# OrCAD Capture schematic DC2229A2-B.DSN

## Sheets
1 -A SHEET1: size C; title: HIGH OUTPUT CURRENT  DUAL OUTPUT STEP-DOWN DC-DC CONVERTER; rev: 2; company: TM
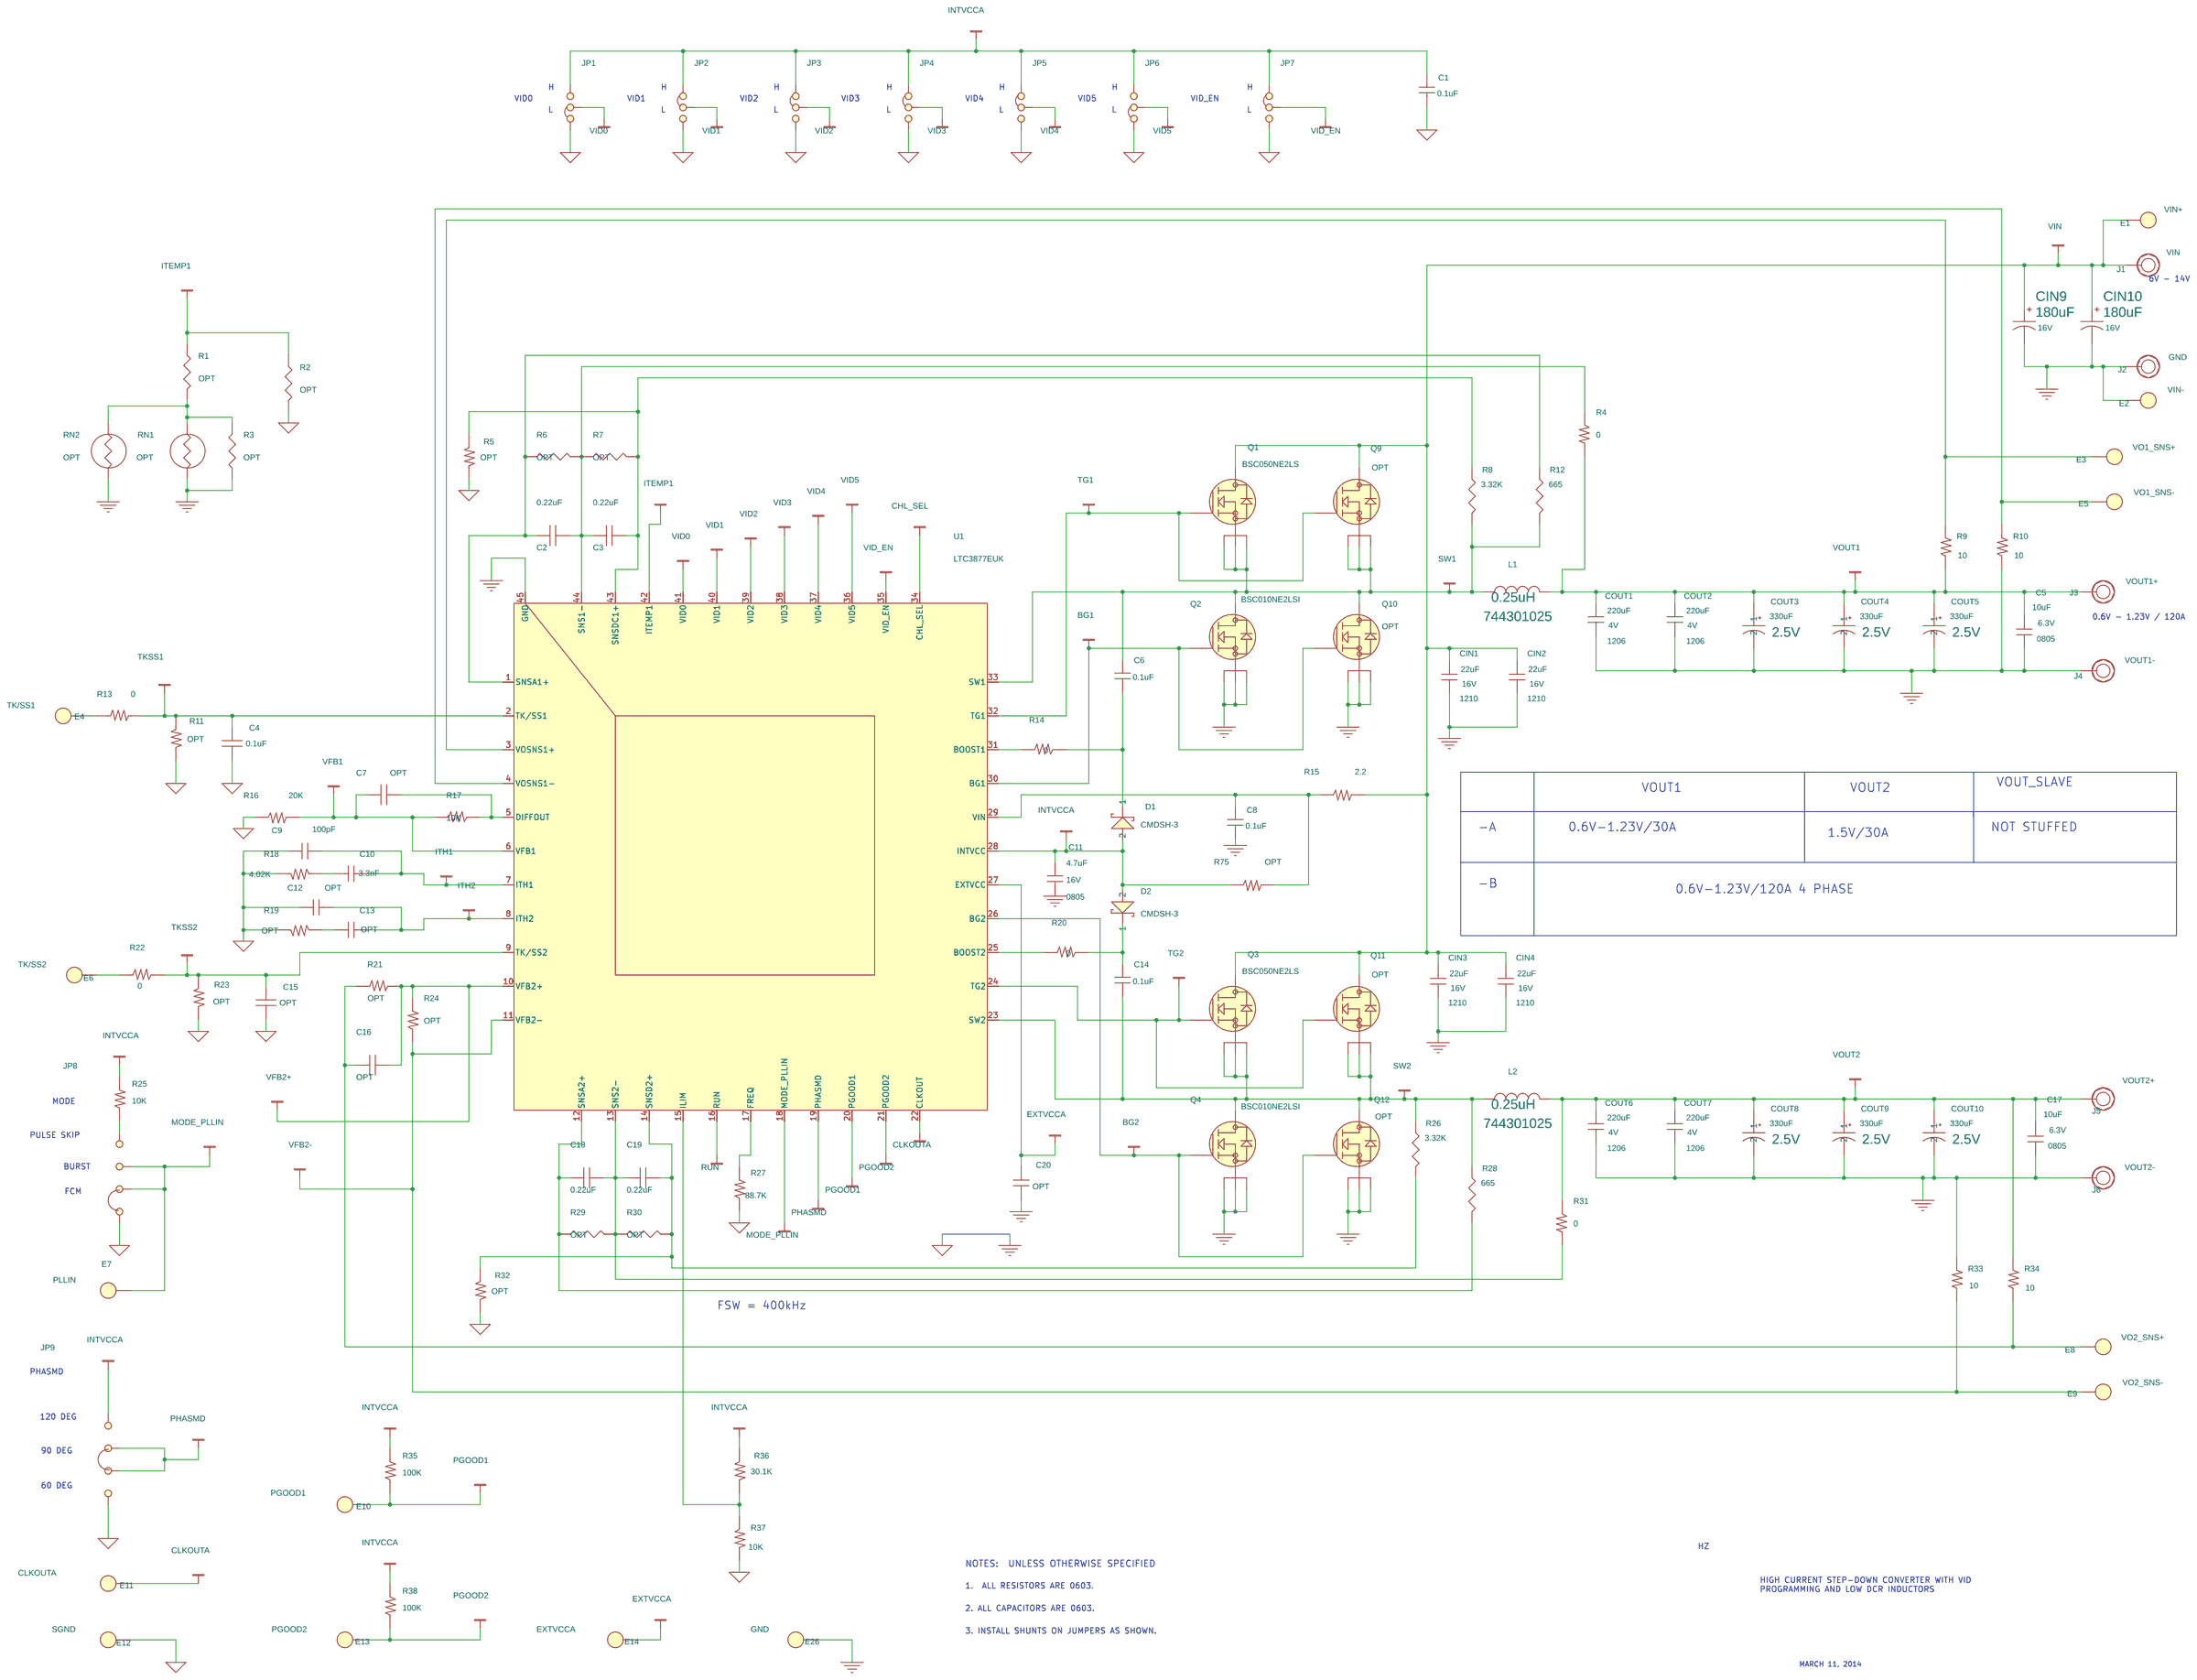
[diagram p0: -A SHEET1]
2 -A SHEET2: size C
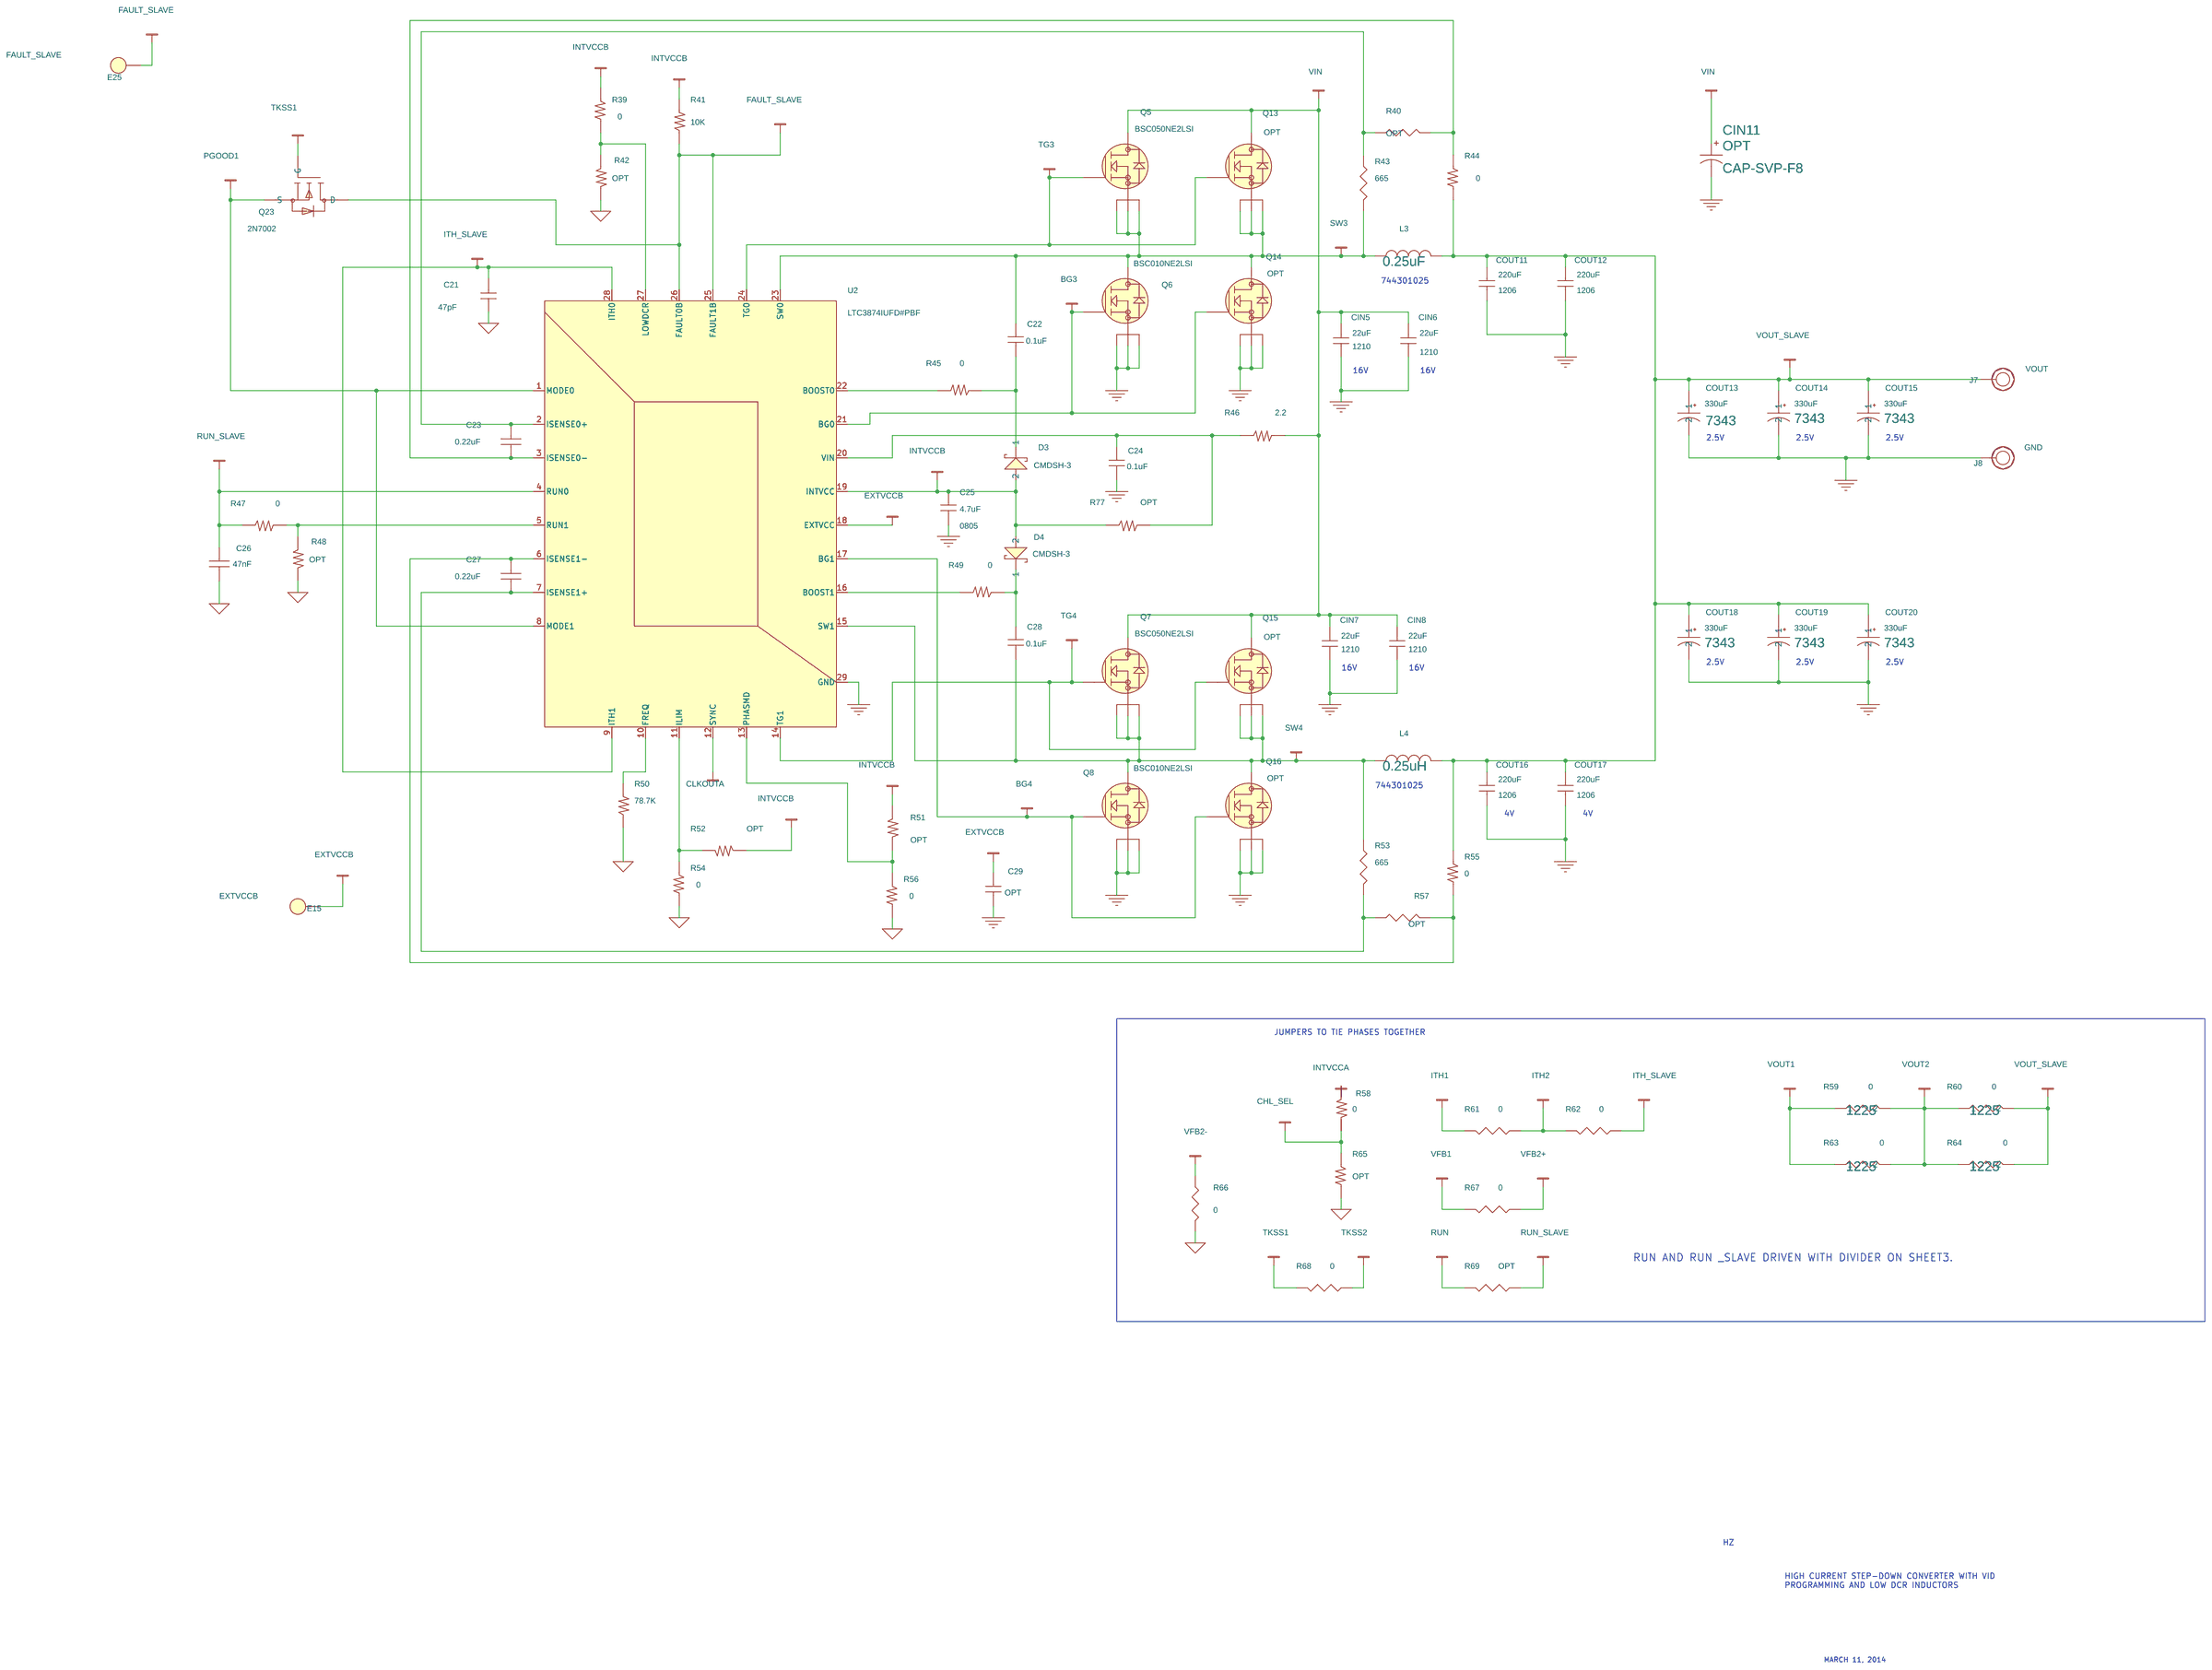
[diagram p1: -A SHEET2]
3 -A SHEET3: size C
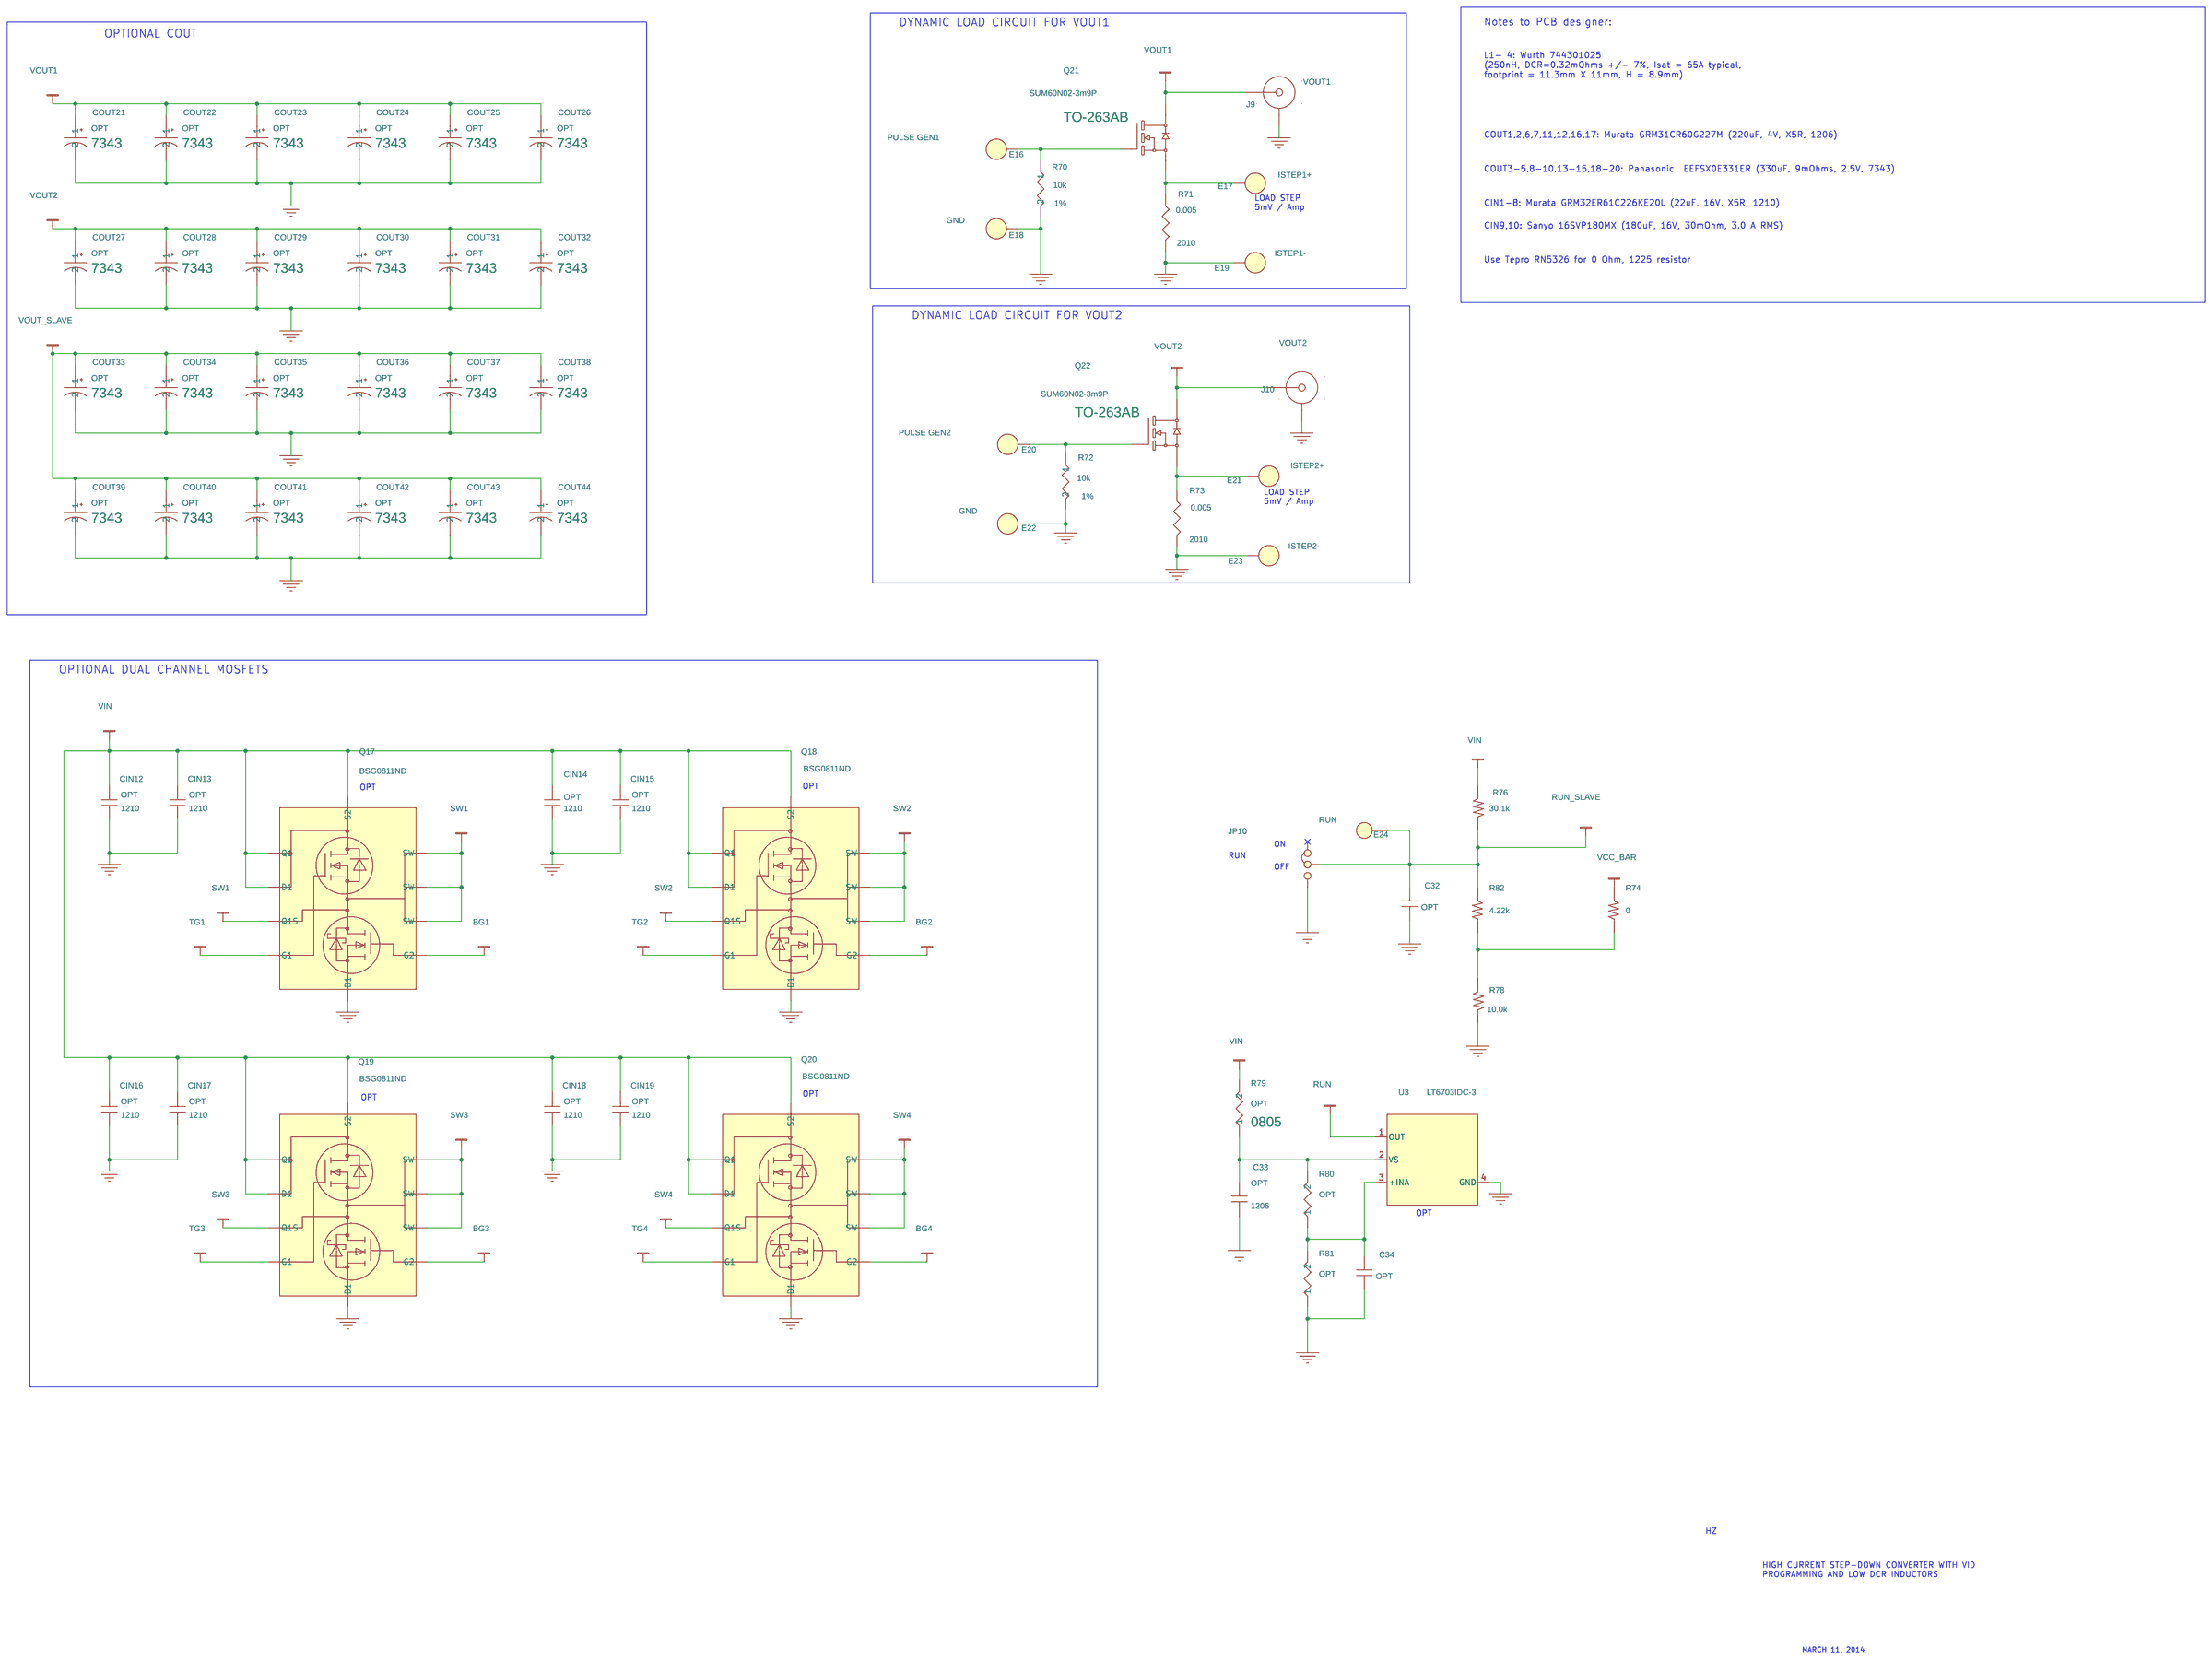
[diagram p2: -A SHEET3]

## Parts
sheet -A SHEET1
C1  0.1uF  [0603]
C2  0.22uF  [0603]
C3  0.22uF  [0603]
C4  0.1uF  [0603]
C5  10uF  [0805]
C6  0.1uF  [0603]
C7  OPT  [0603]
C8  0.1uF  [0603]
C9  100pF  [0603]
C10  3.3nF  [0603]
C11  4.7uF  [0805]
C12  OPT  [0603]
C13  OPT  [0603]
C14  0.1uF  [0603]
C15  OPT  [0603]
C16  OPT  [0603]
C17  10uF  [0805]
C18  0.22uF  [0603]
C19  0.22uF  [0603]
C20  C-0603  [0603]
CIN1  22uF  [1210]
CIN2  22uF  [1210]
CIN3  22uF  [1210]
CIN4  22uF  [1210]
CIN9  180uF  [CAP-SVP-F8]
CIN10  180uF  [CAP-SVP-F8]
COUT1  220uF  [1206]
COUT2  220uF  [1206]
COUT3  330uF  [7343]
COUT4  330uF  [7343]
COUT5  330uF  [7343]
COUT6  220uF  [1206]
COUT7  220uF  [1206]
COUT8  330uF  [7343]
COUT9  330uF  [7343]
COUT10  330uF  [7343]
D1  CMDSH-3  [SOD-323]
D2  CMDSH-3  [SOD-323]
E1  PAD150-094  [PAD150-094]
E2  PAD150-094  [PAD150-094]
E3  PAD150-094  [PAD150-094]
E4  PAD150-094  [PAD150-094]
E5  PAD150-094  [PAD150-094]
E6  PAD150-094  [PAD150-094]
E7  PAD150-094  [PAD150-094]
E8  PAD150-094  [PAD150-094]
E9  PAD150-094  [PAD150-094]
E10  PAD150-094  [PAD150-094]
E11  PAD150-094  [PAD150-094]
E12  PAD150-094  [PAD150-094]
E13  PAD150-094  [PAD150-094]
E14  PAD150-094  [PAD150-094]
E26  PAD150-094  [PAD150-094]
J1  PAD450-190  [CON\LUG\10]
J2  PAD450-190  [CON\LUG\10]
J3  PAD450-190  [CON\LUG\10]
J4  PAD450-190  [CON\LUG\10]
J5  PAD450-190  [CON\LUG\10]
J6  PAD450-190  [CON\LUG\10]
JP1  JMP1X3  [JUMPER3\2MM]
JP2  JMP1X3  [JUMPER3\2MM]
JP3  JMP1X3  [JUMPER3\2MM]
JP4  JMP1X3  [JUMPER3\2MM]
JP5  JMP1X3  [JUMPER3\2MM]
JP6  JMP1X3  [JUMPER3\2MM]
JP7  JMP1X3  [JUMPER3\2MM]
JP8  JP3X1/079\NO\12  [SIP-4P]
JP9  JP3X1/079\NO\12  [SIP-4P]
L1  0.25uH  [744301025]
L2  0.25uH  [744301025]
Q1  BSC050NE2LS  [LFPAK]
Q2  BSC010NE2LSI  [LFPAK]
Q3  BSC050NE2LS  [LFPAK]
Q4  BSC010NE2LSI  [LFPAK]
Q9  LFPAK-OPT  [LFPAK]
Q10  LFPAK-OPT  [LFPAK]
Q11  LFPAK-OPT  [LFPAK]
Q12  LFPAK-OPT  [LFPAK]
R1  OPT  [0603]
R2  OPT  [0603]
R3  OPT  [0603]
R4  0  [0603]
R5  R-0603  [0603]
R6  OPT  [0603]
R7  OPT  [0603]
R8  3.32K  [0603]
R9  10  [0603]
R10  10  [0603]
R11  R-0603  [0603]
R12  665  [0603]
R13  0  [0603]
R14  0  [0603]
R15  2.2  [0603]
R16  20K  [0603]
R17  10K  [0603]
R18  4.02K  [0603]
R19  OPT  [0603]
R20  0  [0603]
R21  OPT  [0603]
R22  0  [0603]
R23  R-0603  [0603]
R24  OPT  [0603]
R25  10K  [0603]
R26  3.32K  [0603]
R27  88.7K  [0603]
R28  665  [0603]
R29  OPT  [0603]
R30  OPT  [0603]
R31  0  [0603]
R32  R-0603  [0603]
R33  10  [0603]
R34  10  [0603]
R35  100K  [0603]
R36  R-0603  [0603]
R37  R-0603  [0603]
R38  100K  [0603]
R75  OPT  [0603]
RN1  OPT  [0603]
RN2  OPT  [0603]
U1  LTC3877EUK  [QFN_44_7MMX7MM_UK]
sheet -A SHEET2
C21  47pF  [0603]
C22  0.1uF  [0603]
C23  0.22uF  [0603]
C24  0.1uF  [0603]
C25  4.7uF  [0805]
C26  47nF  [0603]
C27  0.22uF  [0603]
C28  0.1uF  [0603]
C29  C-0603  [0603]
CIN5  22uF  [1210]
CIN6  22uF  [1210]
CIN7  22uF  [1210]
CIN8  22uF  [1210]
CIN11  OPT  [CAP-SVP-F8]
COUT11  220uF  [1206]
COUT12  220uF  [1206]
COUT13  330uF  [7343]
COUT14  330uF  [7343]
COUT15  330uF  [7343]
COUT16  220uF  [1206]
COUT17  220uF  [1206]
COUT18  330uF  [7343]
COUT19  330uF  [7343]
COUT20  330uF  [7343]
D3  CMDSH-3  [SOD-323]
D4  CMDSH-3  [SOD-323]
E15  PAD150-094  [PAD150-094]
E25  PAD150-094  [PAD150-094]
J7  OPT  [CON\LUG\10]
J8  OPT  [CON\LUG\10]
L3  0.25uF  [744301025]
L4  0.25uH  [744301025]
Q5  BSC050NE2LSI  [LFPAK]
Q6  BSC010NE2LSI  [LFPAK]
Q7  BSC050NE2LSI  [LFPAK]
Q8  BSC010NE2LSI  [LFPAK]
Q13  LFPAK-OPT  [LFPAK]
Q14  LFPAK-OPT  [LFPAK]
Q15  LFPAK-OPT  [LFPAK]
Q16  LFPAK-OPT  [LFPAK]
Q23  2N7002  [SOT-23]
R39  0  [0603]
R40  OPT  [0603]
R41  10K  [0603]
R42  R-0603  [0603]
R43  665  [0603]
R44  0  [0603]
R45  0  [0603]
R46  2.2  [0603]
R47  0  [0603]
R48  R-0603  [0603]
R49  0  [0603]
R50  78.7K  [0603]
R51  OPT  [0603]
R52  OPT  [0603]
R53  665  [0603]
R54  R-0603  [0603]
R55  0  [0603]
R56  R-0603  [0603]
R57  OPT  [0603]
R58  R-0603  [0603]
R59  0  [1225]
R60  0  [1225]
R61  0  [0603]
R62  0  [0603]
R63  0  [1225]
R64  0  [1225]
R65  OPT  [0603]
R66  0  [0603]
R67  0  [0603]
R68  0  [0603]
R69  OPT  [0603]
R77  OPT  [0603]
U2  LTC3874IUFD#PBF  [QFN_28_4MMX5MM_UFD]
sheet -A SHEET3
C32  C-0603  [0603]
C33  OPT  [1206]
C34  C-0603  [0603]
CIN12  OPT  [1210]
CIN13  OPT  [1210]
CIN14  OPT  [1210]
CIN15  OPT  [1210]
CIN16  OPT  [1210]
CIN17  OPT  [1210]
CIN18  OPT  [1210]
CIN19  OPT  [1210]
COUT21  OPT  [7343]
COUT22  OPT  [7343]
COUT23  OPT  [7343]
COUT24  OPT  [7343]
COUT25  OPT  [7343]
COUT26  OPT  [7343]
COUT27  OPT  [7343]
COUT28  OPT  [7343]
COUT29  OPT  [7343]
COUT30  OPT  [7343]
COUT31  OPT  [7343]
COUT32  OPT  [7343]
COUT33  OPT  [7343]
COUT34  OPT  [7343]
COUT35  OPT  [7343]
COUT36  OPT  [7343]
COUT37  OPT  [7343]
COUT38  OPT  [7343]
COUT39  OPT  [7343]
COUT40  OPT  [7343]
COUT41  OPT  [7343]
COUT42  OPT  [7343]
COUT43  OPT  [7343]
COUT44  OPT  [7343]
E16  Testpoint  [PAD150-094]
E17  Testpoint  [PAD150-094]
E18  Testpoint  [PAD150-094]
E19  Testpoint  [PAD150-094]
E20  Testpoint  [PAD150-094]
E21  Testpoint  [PAD150-094]
E22  Testpoint  [PAD150-094]
E23  Testpoint  [PAD150-094]
E24  PAD150-094  [PAD150-094]
J9  Connector  [BNC]
J10  Connector  [BNC]
JP10  JMP1X3  [JUMPER3\2MM]
Q17  BSG0811ND  [PG-TISON8-4]
Q18  BSG0811ND  [PG-TISON8-4]
Q19  BSG0811ND  [PG-TISON8-4]
Q20  BSG0811ND  [PG-TISON8-4]
Q21  SUD50N03-12P  [TO-263AB]
Q22  SUD50N03-12P  [TO-263AB]
R70  10k  [0603]
R71  0.005  [2010]
R72  10k  [0603]
R73  0.005  [2010]
R74  0  [0603]
R76  R-0603  [0603]
R78  R-0603  [0603]
R79  OPT  [0805]
R80  OPT  [0603]
R81  OPT  [0603]
R82  4.22k  [0603]
U3  LT6703IDC-3  [DFN3DC]

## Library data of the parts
C1 C8 C24 = CAP-NP: Voltage: 50V
C2 C3 C18 C19 C23 C27 = EMK107BJ224MA: CAP, 0603 0.22uF 10% 25V X7R; Part Number: TDK C1608X7R1E224K
C4 C7 C15 C16 C26 = EMK107BJ224MA: CAP, X5R, 0.01uF, 25V,10%, 0603; 4th Part Field: AVX; 5th Part Field: 06033C103KAT2A; Part Number: TDK C1608X7R1E224K
C5 C17 = CAP-NP: CAP, 1210 22uF 10% 16V X5R; Part Number: MURATA GRM32ER61C226KE20L; Voltage rating: 6.3V
C6 C11 C14 C22 C25 C28 C33 = CAP-NP: Voltage: 16V
C9 C12 C21 = CAP-NP: CAP, 0603, 100pF; Part Number: TDK C1608X7R1E104K
C10 C13 = CAP-NP: CAP, 0603, 470pF; Part Number: TDK C1608X7R1E104K
C20 C29 C32 C34 = CAP-NP: CAP, 0603; COMPFIXED: OPT; Part Number: TDK C1608X7R1E104K
CIN1-CIN8 CIN12-CIN19 = CAP-NP: CAP, 1210 22uF 10% 16V X5R; Part Number: MURATA GRM32ER61C226KE20L; Voltage rating: 16V
CIN9-CIN11 = CAP: CAP, 180uF 16V; 1ST PART FIELD: 16V; COMPFIXED: Sanyo; COMPGROUP: 16SVP180MX
COUT1 COUT2 COUT6 COUT7 COUT11 COUT12 COUT16 COUT17 = CAP-NP: CAP, 1206 100uF 20% 6.3V X5R; Part Number: MURATA GRM31CR60J107ME39L; Voltage: 4V
COUT3 COUT15 COUT34 = tant_4: CAP, 7343 330uF 20% 2.5V POSCAP; Part Number: SANYO 2R5TPE330M9; Voltage: 2.5V
COUT4 COUT14 COUT24 = tant_3: CAP, 7343 330uF 20% 2.5V POSCAP; Part Number: SANYO 2R5TPE330M9; Voltage: 2.5V
COUT5 COUT20 COUT36 = tant: CAP, 7343 330uF 20% 2.5V POSCAP; Part Number: SANYO 2R5TPE330M9; Voltage: 2.5V
COUT8 COUT19 COUT30 = tant_5: CAP, 7343 330uF 20% 2.5V POSCAP; Part Number: SANYO 2R5TPE330M9; Voltage: 2.5V
COUT9 COUT13 COUT22 = tant_1: CAP, 7343 330uF 20% 2.5V POSCAP; Part Number: SANYO 2R5TPE330M9; Voltage: 2.5V
COUT10 COUT18 COUT35 = tant_2: CAP, 7343 330uF 20% 2.5V POSCAP; Part Number: SANYO 2R5TPE330M9; Voltage: 2.5V
D1 D4 = DIODE-SCHOTTKY_0_1
D2 D3 = DIODE-SCHOTTKY_0
E1 = E: TURRET; COMPFIXED: VIN+; Part Number: MILL-MAX 2501-2-00-80-00-00-07-0
E2 = E: TURRET; COMPFIXED: VIN-; Part Number: MILL-MAX 2501-2-00-80-00-00-07-0
E3 = E: TURRET; COMPFIXED: VO1_SNS+; Part Number: MILL-MAX 2501-2-00-80-00-00-07-0
E4 = E: COMPFIXED: TK/SS1
E5 = E: TURRET; COMPFIXED: VO1_SNS-; Part Number: MILL-MAX 2501-2-00-80-00-00-07-0
E6 = E: COMPFIXED: TK/SS2
E7 = E: COMPFIXED: PLLIN
E8 = E: TURRET; COMPFIXED: VO2_SNS+; Part Number: MILL-MAX 2501-2-00-80-00-00-07-0
E9 = E: TURRET; COMPFIXED: VO2_SNS-; Part Number: MILL-MAX 2501-2-00-80-00-00-07-0
E10 = E: COMPFIXED: PGOOD1
E11 = E: COMPFIXED: CLKOUTA
E12 = E: COMPFIXED: SGND
E13 = E: COMPFIXED: PGOOD2
E14 = E: COMPFIXED: EXTVCCA
E26 = E: COMPFIXED: GND
J1 = E-KEY-575: JACK, BANANA; COMPFIXED: VIN; Part Number: KEYSTONE 575-4
J2 J8 = E-KEY-575: JACK, BANANA; COMPFIXED: GND; Part Number: KEYSTONE 575-4
J3 = E-KEY-575: JACK, BANANA; COMPFIXED: VOUT1+; Part Number: KEYSTONE 575-4
J4 = E-KEY-575: JACK, BANANA; COMPFIXED: VOUT1-; Part Number: KEYSTONE 575-4
J5 = E-KEY-575: JACK, BANANA; COMPFIXED: VOUT2+; Part Number: KEYSTONE 575-4
J6 = E-KEY-575: JACK, BANANA; COMPFIXED: VOUT2-; Part Number: KEYSTONE 575-4
JP1 = JMP1X3_8: HEADER,3PIN, 2mm; Part Number: SAMTEC TMM-103-02-L-S
JP2-JP5 JP7 JP10 = JMP1X3_0: HEADER,3PIN, 2mm; Part Number: SAMTEC TMM-103-02-L-S
JP6 = JMP1X3_9: HEADER,3PIN, 2mm; Part Number: SAMTEC TMM-103-02-L-S
JP8 = JP3X1_079_NO_12_0
JP9 = JP3X1_079_NO_12_5
L1-L4 = IND
Q1 Q3 Q5 Q7 = MOSFET_N-DIODE-A-LFPAK_0
Q2 Q4 Q6 Q8 = MOSFET_N-DIODE-A-LFPAK
Q9-Q16 = MOSFET_N-DIODE-A-LFPAK: COMPFIXED: OPT
R1-R3 R6 R7 R29 R30 R40 R57 R61 R62 R66-R69 = R: RES, 0603 OPTION; Part Number: OPTION
R4 R13-R17 R20-R22 R24 R25 R27 R31 R35 R38 R39 R41 R44-R47 R49-R52 R55 R65 R74 R75 R77 R82 = R_v2
R5 R11 R23 R32 R42 R48 = R_v2: RES, 0603; COMPFIXED: OPT; Part Number: PANASONIC ERJ3GEY0R00V
R8 R12 R26 R28 R43 R53 = CRCW06032K87FKEA
R9 R10 R33 R34 = R_v2: RES, 0603; Part Number: PANASONIC ERJ3GEY0R00V
R18 R19 = R_v2: RES, 0603, 10K; Part Number: PANASONIC ERJ3GEY0R00V
R36 = R_v2: RES, 0603; COMPFIXED: 30.1K; Part Number: PANASONIC ERJ3GEY0R00V
R37 = R_v2: RES, 0603; COMPFIXED: 10K; Part Number: PANASONIC ERJ3GEY0R00V
RN1 RN2 = RNTC: THERMISTOR, 0805 100K OHMS 5% / 0603 4250 OHMS 2%; Part Number: MURATA NCP18WF104J03RB /
U1 = LTC1629_26: IC, LTC3838EUHF; Part Number: LINEAR TECH. LTC3838EUHF
E15 = E: COMPFIXED: EXTVCCB
E25 = E: COMPFIXED: FAULT_SLAVE
J7 = E-KEY-575: JACK, BANANA; COMPFIXED: VOUT; Part Number: KEYSTONE 575-4
Q23 = TRANSISTOR_0: XSTR, N-CHANNEL DMOS FET; Part Number: FAIRCHILD 2N7002A
R54 R56 R58 = R_v2: RES, 0603; COMPFIXED: 0; Part Number: PANASONIC ERJ3GEY0R00V
R59 = CR16-104JM_3: RES, OPT, 2512
R60 = CR16-104JM_2: RES, OPT, 2512
R63 = CR16-104JM_1: RES, OPT, 2512
R64 = CR16-104JM: RES, OPT, 2512
U2 = LTC3880-M0001_1: IC, POLYPHASE STEP-DOWN SYNCHRONOUS SLAVE CONTROLLER; Component: IC; Manufacturer: LTC; Manufacturer P/N: LTC3880_M0001; Part Number: LINEAR TECH.LTC3874IUFD#PBF; Part Type: LTC3880EUF
COUT21 = tant_22: CAP, 7343 330uF 20% 2.5V POSCAP; Part Number: SANYO 2R5TPE330M9; Voltage: 2.5V
COUT23 = tant_21: CAP, 7343 330uF 20% 2.5V POSCAP; Part Number: SANYO 2R5TPE330M9; Voltage: 2.5V
COUT25 = tant_20: CAP, 7343 330uF 20% 2.5V POSCAP; Part Number: SANYO 2R5TPE330M9; Voltage: 2.5V
COUT26 = tant_16: CAP, 7343 330uF 20% 2.5V POSCAP; Part Number: SANYO 2R5TPE330M9; Voltage: 2.5V
COUT27 = tant_17: CAP, 7343 330uF 20% 2.5V POSCAP; Part Number: SANYO 2R5TPE330M9; Voltage: 2.5V
COUT28 = tant_8: CAP, 7343 330uF 20% 2.5V POSCAP; Part Number: SANYO 2R5TPE330M9; Voltage: 2.5V
COUT29 = tant_6: CAP, 7343 330uF 20% 2.5V POSCAP; Part Number: SANYO 2R5TPE330M9; Voltage: 2.5V
COUT31 = tant_14: CAP, 7343 330uF 20% 2.5V POSCAP; Part Number: SANYO 2R5TPE330M9; Voltage: 2.5V
COUT32 = tant_12: CAP, 7343 330uF 20% 2.5V POSCAP; Part Number: SANYO 2R5TPE330M9; Voltage: 2.5V
COUT33 = tant_11: CAP, 7343 330uF 20% 2.5V POSCAP; Part Number: SANYO 2R5TPE330M9; Voltage: 2.5V
COUT37 = tant_9: CAP, 7343 330uF 20% 2.5V POSCAP; Part Number: SANYO 2R5TPE330M9; Voltage: 2.5V
COUT38 = tant_7: CAP, 7343 330uF 20% 2.5V POSCAP; Part Number: SANYO 2R5TPE330M9; Voltage: 2.5V
COUT39 = tant_19: CAP, 7343 330uF 20% 2.5V POSCAP; Part Number: SANYO 2R5TPE330M9; Voltage: 2.5V
COUT40 = tant_18: CAP, 7343 330uF 20% 2.5V POSCAP; Part Number: SANYO 2R5TPE330M9; Voltage: 2.5V
COUT41 = tant_13: CAP, 7343 330uF 20% 2.5V POSCAP; Part Number: SANYO 2R5TPE330M9; Voltage: 2.5V
COUT42 = tant_10: CAP, 7343 330uF 20% 2.5V POSCAP; Part Number: SANYO 2R5TPE330M9; Voltage: 2.5V
COUT43 = tant_23: CAP, 7343 330uF 20% 2.5V POSCAP; Part Number: SANYO 2R5TPE330M9; Voltage: 2.5V
COUT44 = tant_15: CAP, 7343 330uF 20% 2.5V POSCAP; Part Number: SANYO 2R5TPE330M9; Voltage: 2.5V
E16 = MillMax-2501: TURRET; 9th Part Field: PULSE GEN1; Part Number: MILL MAX 2501-2-00-80-00-00-07-0
E17 = MillMax-2501: TURRET; 9th Part Field: ISTEP1+; Part Number: MILL MAX 2501-2-00-80-00-00-07-0
E18 E22 = MillMax-2501: TURRET; 9th Part Field: GND; Part Number: MILL MAX 2501-2-00-80-00-00-07-0
E19 = MillMax-2501: TURRET; 9th Part Field: ISTEP1-; Part Number: MILL MAX 2501-2-00-80-00-00-07-0
E20 = MillMax-2501: TURRET; 9th Part Field: PULSE GEN2; Part Number: MILL MAX 2501-2-00-80-00-00-07-0
E21 = MillMax-2501: TURRET; 9th Part Field: ISTEP2+; Part Number: MILL MAX 2501-2-00-80-00-00-07-0
E23 = MillMax-2501: TURRET; 9th Part Field: ISTEP2-; Part Number: MILL MAX 2501-2-00-80-00-00-07-0
E24 = E: COMPFIXED: RUN
J9 = Connex_112404_gnd2_0: CON, BNC, 5 PINS; 10th Part Field: 5% DUTY CYCLE MAX.; 11th Part Field: 10mV / A; 9th Part Field: VOUT1; Part Number: CONNEX 112404
J10 = Connex_112404_gnd2_0_1: CON, BNC, 5 PINS; 10th Part Field: 5% DUTY CYCLE MAX.; 11th Part Field: 10mV / A; 9th Part Field: VOUT2; Part Number: CONNEX 112404
Q17-Q20 = FDMS3602S_8
Q21 Q22 = Si7806BDN_0: XSTR, MOSFET; 5th Part Field: SUM60N02-3m9P; Part Number: VISHAY SILICONIX SUD50N03-12P
R70 = CR16-103JM_3: RES, 0603 10K OHMS 1% 1/10W; 2nd Part Field: 1%; Part Number: NIC NRC06F1002TRF
R71 = LR2010-01-R020-F_1: RES. 2010 0.010 OHMS 2% 1W; 5th Part Field: LR2010-01-R010-F; Part Number: IRC LRC-LRF2010LF-01-R010-F
R72 = CR16-103JM_4: RES, 0603 10K OHMS 1% 1/10W; 2nd Part Field: 1%; Part Number: NIC NRC06F1002TRF
R73 = LR2010-01-R020-F: RES. 2010 0.010 OHMS 2% 1W; 5th Part Field: LR2010-01-R010-F; Part Number: IRC LRC-LRF2010LF-01-R010-F
R76 = R_v2: RES, 0603; COMPFIXED: 30.1k; Part Number: PANASONIC ERJ3GEY0R00V
R78 = R_v2: RES, 0603; COMPFIXED: 10.0k; Part Number: PANASONIC ERJ3GEY0R00V
R79 = CR16-103JM: RES, 0603 10 OHMS 5% 1/10W; Part Number: YAGEO RC0603JR-0710RL
R80 = CR16-103JM_1: RES, 0603 10 OHMS 5% 1/10W; Part Number: YAGEO RC0603JR-0710RL
R81 = CR16-103JM_2: RES, 0603 10 OHMS 5% 1/10W; Part Number: YAGEO RC0603JR-0710RL
U3 = LT3010EMS8E_6: IC, Micropower, Low Voltage Comparator; Part Number: LINEAR TECH LT6703IDC-3

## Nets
Agnd: C1.2 C4.2 C9.1 C12.1 C15.2 C21.1 C26.2 E12.1(A) JP1.3 JP2.3 JP3.3 JP4.3 JP5.3 JP6.3 JP7.3 JP8.1 JP9.4 R2.1 R5.2 R11.2 R16.1 R18.2 R19.2 R23.2 R27.1 R32.2 R37.2 R42.2 R48.2 R50.1 R54.2 R56.2 R65.2 R66.2
GND: C5.1 C8.2 C11.2 C17.1 C20.2 C24.2 C25.2 C29.2 C32.2 C33.2 C34.2 CIN1.1 CIN2.1 CIN3.1 CIN4.1 CIN5.1 CIN6.1 CIN7.1 CIN8.1 CIN9.2 CIN10.2 CIN11.2 CIN12.1 CIN13.1 CIN14.1 CIN15.1 CIN16.1 CIN17.1 CIN18.1 CIN19.1 COUT1.2 COUT2.2 COUT3.2 COUT4.2 COUT5.2 COUT6.2 COUT7.2 COUT8.2 COUT9.2 COUT10.2 COUT11.2 COUT12.2 COUT13.2 COUT14.2 COUT15.2 COUT16.2 COUT17.2 COUT18.2 COUT19.2 COUT20.2 COUT21.2 COUT22.2 COUT23.2 COUT24.2 COUT25.2 COUT26.2 COUT27.2 COUT28.2 COUT29.2 COUT30.2 COUT31.2 COUT32.2 COUT33.2 COUT34.2 COUT35.2 COUT36.2 COUT37.2 COUT38.2 COUT39.2 COUT40.2 COUT41.2 COUT42.2 COUT43.2 COUT44.2 E2.1(A) E18.1 E19.1 E22.1 E23.1 E26.1(A) J2.1 J4.1 J6.1 J8.1 J9.2(GND2) J9.3(GND) J9.4(GND) J9.5(GND) J10.2(GND2) J10.3(GND) J10.4(GND) J10.5(GND) JP10.3 Q2.1 Q2.2 Q2.3 Q4.1 Q4.2 Q4.3 Q6.1 Q6.2 Q6.3 Q8.1 Q8.2 Q8.3 Q10.1 Q10.2 Q10.3 Q12.1 Q12.2 Q12.3 Q14.1 Q14.2 Q14.3 Q16.1 Q16.2 Q16.3 Q17.10(D1) Q18.10(D1) Q19.10(D1) Q20.10(D1) R3.1 R10.1 R33.2 R70.2 R71.2 R72.2 R73.2 R78.2 R81.1 RN1.1 RN2.1 U1.45(GND) U2.29(GND) U3.4(GND)
VIN: CIN1.2 CIN2.2 CIN3.2 CIN4.2 CIN5.2 CIN6.2 CIN7.2 CIN8.2 CIN9.1 CIN10.1 CIN11.1 CIN12.2 CIN13.2 CIN14.2 CIN15.2 CIN16.2 CIN17.2 CIN18.2 CIN19.2 E1.1(A) J1.1 Q1.5 Q3.5 Q5.5 Q7.5 Q9.5 Q11.5 Q13.5 Q15.5 Q17.3(D1) Q17.4(Q1) Q17.9(S2) Q18.3(D1) Q18.4(Q1) Q18.9(S2) Q19.3(D1) Q19.4(Q1) Q19.9(S2) Q20.3(D1) Q20.4(Q1) Q20.9(S2) R15.2 R46.2 R76.1 R79.2
BG1: Q2.4 Q10.4 Q17.8(G2) U1.30(BG1)
BG2: Q4.4 Q12.4 Q18.8(G2) U1.26(BG2)
BG3: Q6.4 Q14.4 Q19.8(G2) U2.21(BG0)
BG4: Q8.4 Q16.4 Q20.8(G2) U2.17(BG1)
CHL_SEL: R58.2 R65.1 U1.34(CHL_SEL)
CLKOUTA: E11.1(A) U1.22(CLKOUT) U2.12(SYNC)
EXTVCCA: C20.1 E14.1(A) U1.27(EXTVCC)
EXTVCCB: C29.1 E15.1(A) U2.18(EXTVCC)
FAULT_SLAVE: E25.1(A) Q23.3(D) R41.1 U2.25(FAULT1B) U2.26(FAULT0B)
INTVCCA: C1.1 C11.1 D1.2 D2.2 JP1.1 JP2.1 JP3.1 JP4.1 JP5.1 JP6.1 JP7.1 JP9.1 R25.2 R35.2 R36.1 R38.2 R58.1 R75.1 U1.28(INTVCC)
INTVCCB: C25.1 D3.2 D4.2 R39.1 R41.2 R51.1 R52.1 R77.1 U2.19(INTVCC)
ITEMP1: R1.2 R2.2 U1.42(ITEMP1)
ITH1: C9.2 C10.1 R61.2 U1.7(ITH1)
ITH2: C12.2 C13.1 R61.1 R62.2 U1.8(ITH2)
ITH_SLAVE: C21.2 R62.1 U2.9(ITH1) U2.28(ITH0)
MODE_PLLIN: E7.1(A) JP8.2 JP8.3 U1.18(MODE_PLLIN)
PGOOD1: E10.1(A) Q23.2(S) R35.1 U1.20(PGOOD1) U2.1(MODE0) U2.8(MODE1)
PGOOD2: E13.1(A) R38.1 U1.21(PGOOD2)
PHASMD: JP9.2 JP9.3 U1.19(PHASMD)
RUN: R69.2 R74.1 U1.16(RUN) U3.1(OUT)
RUN_SLAVE: C26.1 C32.1 E24.1(A) JP10.2 R47.1 R69.1 R76.2 R82.1 U2.4(RUN0)
SW1: C6.1 L1.1 Q1.1 Q1.2 Q1.3 Q2.5 Q9.1 Q9.2 Q9.3 Q10.5 Q17.2(Q1S) Q17.5(SW) Q17.6(SW) Q17.7(SW) R8.2 R12.2 U1.33(SW1)
SW2: C14.2 L2.1 Q3.1 Q3.2 Q3.3 Q4.5 Q11.1 Q11.2 Q11.3 Q12.5 Q18.2(Q1S) Q18.5(SW) Q18.6(SW) Q18.7(SW) R26.1 R28.1 U1.23(SW2)
SW3: C22.1 L3.1 Q5.1 Q5.2 Q5.3 Q6.5 Q13.1 Q13.2 Q13.3 Q14.5 Q19.2(Q1S) Q19.5(SW) Q19.6(SW) Q19.7(SW) R43.2 U2.23(SW0)
SW4: C28.2 L4.1 Q7.1 Q7.2 Q7.3 Q8.5 Q15.1 Q15.2 Q15.3 Q16.5 Q20.2(Q1S) Q20.5(SW) Q20.6(SW) Q20.7(SW) R53.1 U2.15(SW1)
TG1: Q1.4 Q9.4 Q17.1(G1) U1.32(TG1)
TG2: Q3.4 Q11.4 Q18.1(G1) U1.24(TG2)
TG3: Q5.4 Q13.4 Q19.1(G1) U2.24(TG0)
TG4: Q7.4 Q15.4 Q20.1(G1) U2.14(TG1)
TKSS1: C4.1 Q23.1(G) R11.1 R13.1 R68.2 U1.2(TK/SS1)
TKSS2: C15.1 R22.1 R23.1 R68.1 U1.9(TK/SS2)
VFB1: C7.1 R16.2 R17.2 R67.2 U1.6(VFB1)
VFB2+: C16.2 R21.1 R24.2 R67.1 U1.10(VFB2+)
VFB2-: E9.1(A) R24.1 R33.1 R66.1 U1.11(VFB2-)
VID0: JP1.2 U1.41(VID0)
VID1: JP2.2 U1.40(VID1)
VID2: JP3.2 U1.39(VID2)
VID3: JP4.2 U1.38(VID3)
VID4: JP5.2 U1.37(VID4)
VID5: JP6.2 U1.36(VID5)
VID_EN: JP7.2 U1.35(VID_EN)
VOUT1: C5.2 COUT1.1 COUT2.1 COUT3.1 COUT4.1 COUT5.1 COUT21.1 COUT22.1 COUT23.1 COUT24.1 COUT25.1 COUT26.1 J3.1 J9.1 L1.2 Q21.2(D) R4.2 R9.1 R59.1 R63.1
VOUT2: C17.2 COUT6.1 COUT7.1 COUT8.1 COUT9.1 COUT10.1 COUT27.1 COUT28.1 COUT29.1 COUT30.1 COUT31.1 COUT32.1 J5.1 J10.1 L2.2 Q22.2(D) R31.1 R34.2 R59.2 R60.1 R63.2 R64.1
VOUT_SLAVE: COUT11.1 COUT12.1 COUT13.1 COUT14.1 COUT15.1 COUT16.1 COUT17.1 COUT18.1 COUT19.1 COUT20.1 COUT33.1 COUT34.1 COUT35.1 COUT36.1 COUT37.1 COUT38.1 COUT39.1 COUT40.1 COUT41.1 COUT42.1 COUT43.1 COUT44.1 J7.1 L3.2 L4.2 R44.2 R55.1 R60.2 R64.2
N22153159: E17.1 Q21.3(S) R71.1
N22153163: E21.1 Q22.3(S) R73.1
N22153165: E20.1 Q22.1(G) R72.1
N22153171: E16.1 Q21.1(G) R70.1
N22327388: C22.2 D3.1 R45.1
N22327390: R45.2 U2.22(BOOST0)
N22327426: C28.1 D4.1 R49.1
N22327434: R49.2 U2.16(BOOST1)
N22327450: C27.1 R53.2 R57.2 U2.7(ISENSE1+)
N22328210: C27.2 R55.2 R57.1 U2.6(ISENSE1-)
N22382799: C24.1 R46.1 R77.2 U2.20(VIN)
N22419626: C23.2 R40.2 R43.1 U2.2(ISENSE0+)
N22420599: C23.1 R40.1 R44.1 U2.3(ISENSE0-)
N22444159: R39.2 R42.1 U2.27(LOWDCR)
N22464024: R50.2 U2.10(FREQ)
N22470021: R52.2 R54.1 U2.11(ILIM)
N22503485: R47.2 R48.1 U2.5(RUN1)
N22569756: R51.2 R56.1 U2.13(PHASMD)
N22723294: JP8.4 R25.1
N22723414: R14.2 U1.31(BOOST1)
N22723415: C6.2 D1.1 R14.1
N22723421: R20.2 U1.25(BOOST2)
N22723424: C14.1 D2.1 R20.1
N22723428: C8.1 R15.1 R75.2 U1.29(VIN)
N22723436: C13.2 R19.1
N22723440: C16.1 E8.1(A) R21.2 R34.1
N22723453: C18.2 C19.1 R29.1 R30.2 R31.2 U1.13(SNS2-)
N22723454: C19.2 R26.2 R30.1 R32.1 U1.14(SNSD2+)
N22723459: C18.1 R28.2 R29.2 U1.12(SNSA2+)
N22723469: C3.2 R5.1 R7.1 R8.1 U1.43(SNSDC1+)
N22723472: C2.2 C3.1 R4.1 R6.1 R7.2 U1.44(SNS1-)
N22723474: C2.1 R6.2 R12.1 U1.1(SNSA1+)
N22723531: C10.2 R18.1
N22723541: E3.1(A) R9.2 U1.3(VOSNS1+)
N22723545: E5.1(A) R10.2 U1.4(VOSNS1-)
N22723565: E4.1(A) R13.2
N22723572: R27.2 U1.17(FREQ)
N22723580: R36.2 R37.1 U1.15(ILIM)
N22723736: E6.1(A) R22.2
N22781756: R1.1 R3.2 RN1.2 RN2.2
N22826857: C7.2 R17.1 U1.5(DIFFOUT)
N23587988: C34.1 R80.1 R81.2 U3.3(+INA)
N23587996: R74.2 R78.1 R82.2
N23588043: C33.1 R79.1 R80.2 U3.2(VS)

Not connected (* = marked no-connect by the designer): JP10 1*

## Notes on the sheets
sheet 1
- H
- H
- H
- H
- H
- H
- H
- VID0
- VID1
- VID2
- VID3
- VID4
- VID5
- VID_EN
- L
- L
- L
- L
- L
- L
- L
- 6V - 14V
- 0.6V - 1.23V / 120A
- VOUT_SLAVE
- VOUT1
- VOUT2
- -A
- 0.6V-1.23V/30A
- NOT STUFFED
- 1.5V/30A
- -B
- 0.6V-1.23V/120A 4 PHASE
- MODE
- PULSE SKIP
- BURST
- FCM
- FSW = 400kHz
- PHASMD
- 120 DEG
- 90 DEG
- 60 DEG
- HZ
- NOTES:  UNLESS OTHERWISE SPECIFIED
- HIGH CURRENT STEP-DOWN CONVERTER WITH VID
  PROGRAMMING AND LOW DCR INDUCTORS
- 1.  ALL RESISTORS ARE 0603.
- 2. ALL CAPACITORS ARE 0603.
- 3. INSTALL SHUNTS ON JUMPERS AS SHOWN.
- MARCH 11, 2014
sheet 2
- 744301025
- 16V
- 16V
- 2.5V
- 2.5V
- 2.5V
- 2.5V
- 2.5V
- 2.5V
- 16V
- 16V
- 744301025
- 4V
- 4V
- JUMPERS TO TIE PHASES TOGETHER
- RUN AND RUN _SLAVE DRIVEN WITH DIVIDER ON SHEET3.
- HZ
- HIGH CURRENT STEP-DOWN CONVERTER WITH VID
  PROGRAMMING AND LOW DCR INDUCTORS
- MARCH 11, 2014
sheet 3
- DYNAMIC LOAD CIRCUIT FOR VOUT1
- Notes to PCB designer:
- OPTIONAL COUT
- L1- 4: Wurth 744301025
  (250nH, DCR=0.32mOhms +/- 7%, Isat = 65A typical,
  footprint = 11.3mm X 11mm, H = 8.9mm)
- COUT1,2,6,7,11,12,16,17: Murata GRM31CR60G227M (220uF, 4V, X5R, 1206)
- COUT3-5,8-10,13-15,18-20: Panasonic  EEFSX0E331ER (330uF, 9mOhms, 2.5V, 7343)
- LOAD STEP
  5mV / Amp
- CIN1-8: Murata GRM32ER61C226KE20L (22uF, 16V, X5R, 1210)
- CIN9,10: Sanyo 16SVP180MX (180uF, 16V, 30mOhm, 3.0 A RMS)
- Use Tepro RN5326 for 0 Ohm, 1225 resistor
- DYNAMIC LOAD CIRCUIT FOR VOUT2
- LOAD STEP
  5mV / Amp
- OPTIONAL DUAL CHANNEL MOSFETS
- OPT
- OPT
- ON
- RUN
- OFF
- OPT
- OPT
- OPT
- HZ
- HIGH CURRENT STEP-DOWN CONVERTER WITH VID
  PROGRAMMING AND LOW DCR INDUCTORS
- MARCH 11, 2014
